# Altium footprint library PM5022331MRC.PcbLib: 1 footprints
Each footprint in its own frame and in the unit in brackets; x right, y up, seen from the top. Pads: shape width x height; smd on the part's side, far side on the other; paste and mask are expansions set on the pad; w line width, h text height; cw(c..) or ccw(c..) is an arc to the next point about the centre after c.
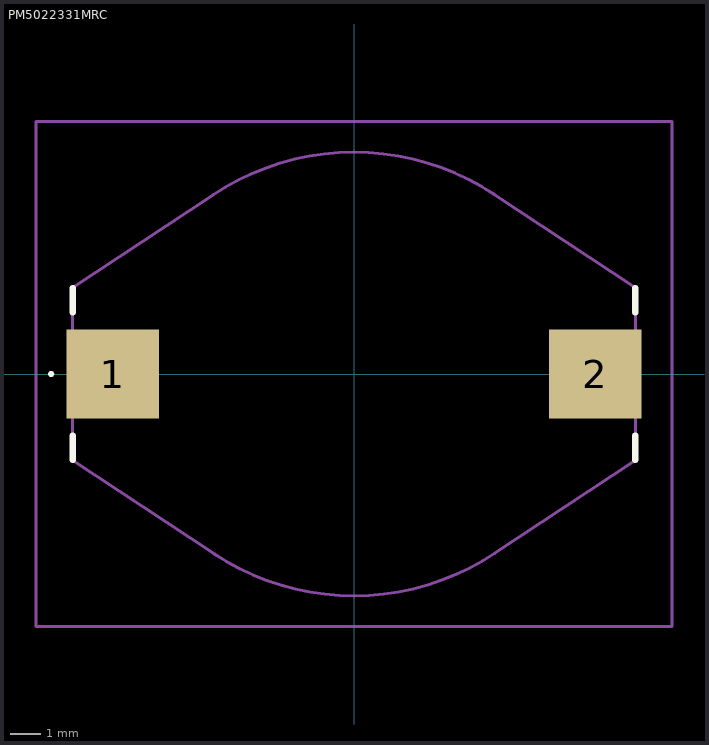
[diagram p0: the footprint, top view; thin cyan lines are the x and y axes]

## PM5022331MRC [mm]
pads (2):
  rect 3x2.9 smd: 1(-7.85,0) 2(7.85,0)
Top Overlay:
  lines w0.1: -9.9,0 cw(c-9.85,0) -9.8,0 ; -9.9,0 -9.9,0 ; -9.9,0 ccw(c-9.85,0) -9.8,0 ; -9.8,0 -9.8,0
  lines w0.2: -9.15,-2.8 -9.15,-2 ; -9.15,2 -9.15,2.8 ; 9.15,-2.8 9.15,-2 ; 9.15,2 9.15,2.8
Mechanical 15:
  lines w0.1: -4.58,5.832 cw(c0,-1.061) 4.568,5.84 ; -4.575,-5.835 -9.15,-2.8 -9.15,2.8 -4.575,5.835 ; -4.568,-5.84 ccw(c0,1.061) 4.58,-5.832 ; 4.575,5.835 9.15,2.8 9.15,-2.8 4.575,-5.835 ; -4.575,5.835 -4.575,5.835 ; 4.575,-5.835 4.575,-5.835
Mechanical 20:
  lines w0.1: -10.35,-8.215 10.35,-8.215 10.35,8.215 -10.35,8.215 -10.35,-8.215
